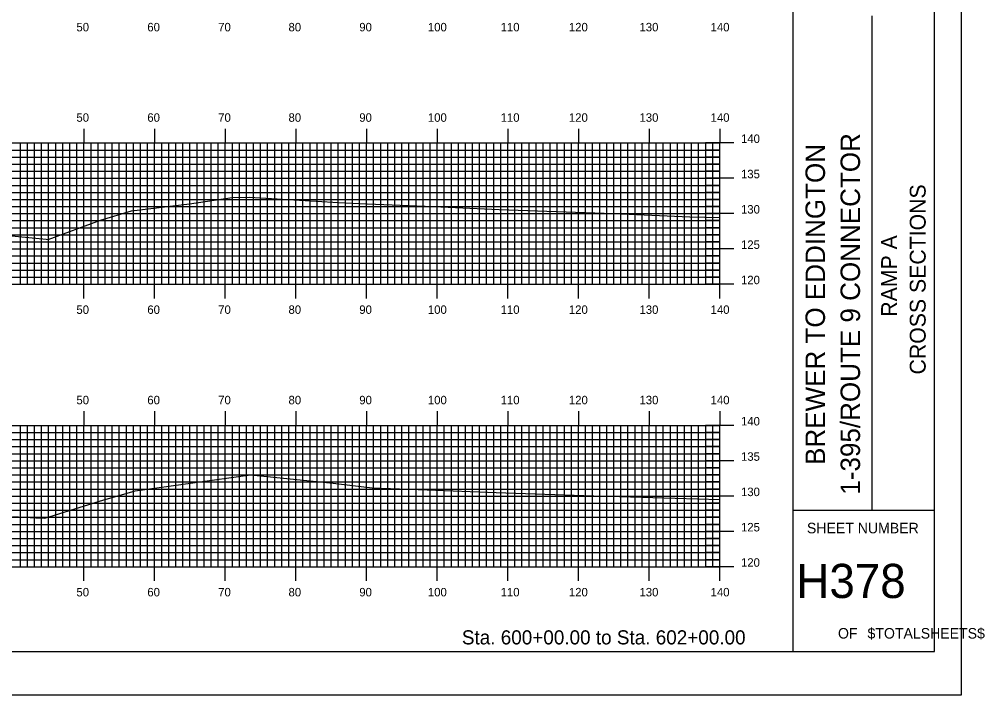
# Model space of a CAD drawing. Extents: x 841388 to 841731, y 363538 to 363758.
# Drawn here: x 841594.7 to 841731.4, y 363537.6 to 363633.2 of the extents above; entities that cross this region are included whole.
import ezdxf

# ---------------------------------------------------------------- set-up
doc = ezdxf.new("R2010")
doc.units = 0
for name, color, linetype in [('BORDER', 7, 'Continuous'), ('H_V ANNOTATION', 7, 'Continuous'), ('MAJOR', 7, 'Continuous'), ('MINOR', 7, 'Continuous'), ('PLOT BOUNDARY', 7, 'Continuous'), ('S_Roadway_Centerline', 7, 'Continuous')]:
    doc.layers.add(name, color=color, linetype=linetype)

msp = doc.modelspace()

# ---------------------------------------------------------------- linework, layer by layer
at = {"layer": 'BORDER'}
for p, q in [((841704.26, 363543.72), (841704.26, 363753.72)), ((841715.44, 363563.73), (841715.44, 363633.73)), ((841704.26, 363563.73), (841724.26, 363563.73))]:
    msp.add_line(p, q, dxfattribs=at)
msp.add_lwpolyline([(841404.26, 363543.72), (841724.26, 363543.72), (841724.26, 363753.72), (841404.26, 363753.72)], close=True, dxfattribs=at)
at = {"layer": 'MAJOR'}
for p, q in [((841603.86, 363617.73), (841603.86, 363615.72)), ((841613.86, 363617.73), (841613.86, 363615.72)), ((841623.86, 363617.73), (841623.86, 363615.72)), ((841633.86, 363617.73), (841633.86, 363615.72)), ((841643.86, 363617.73), (841643.86, 363615.72)), ((841653.86, 363617.73), (841653.86, 363615.72)), ((841663.86, 363617.73), (841663.86, 363615.72)), ((841673.86, 363617.73), (841673.86, 363615.72)), ((841683.86, 363617.73), (841683.86, 363615.72)), ((841693.86, 363617.73), (841693.86, 363615.72)), ((841413.86, 363615.72), (841693.86, 363615.72)), ((841413.86, 363615.72), (841693.86, 363615.72)), ((841603.86, 363595.72), (841603.86, 363615.72)), ((841613.86, 363595.72), (841613.86, 363615.72)), ((841623.86, 363595.72), (841623.86, 363615.72)), ((841633.86, 363595.72), (841633.86, 363615.72)), ((841643.86, 363595.72), (841643.86, 363615.72)), ((841653.86, 363595.72), (841653.86, 363615.72)), ((841663.86, 363595.72), (841663.86, 363615.72)), ((841673.86, 363595.72), (841673.86, 363615.72)), ((841683.86, 363595.72), (841683.86, 363615.72)), ((841695.86, 363615.72), (841691.85, 363615.72)), ((841693.86, 363595.72), (841693.86, 363615.72)), ((841693.86, 363595.72), (841693.86, 363615.72)), ((841413.86, 363610.72), (841693.86, 363610.72)), ((841695.86, 363610.72), (841691.85, 363610.72)), ((841413.86, 363605.72), (841693.86, 363605.72)), ((841695.86, 363605.72), (841691.85, 363605.72)), ((841413.86, 363600.72), (841693.86, 363600.72)), ((841695.86, 363600.72), (841691.85, 363600.72)), ((841413.86, 363595.72), (841693.86, 363595.72)), ((841413.86, 363595.72), (841693.86, 363595.72)), ((841603.86, 363593.72), (841603.86, 363595.72)), ((841613.86, 363593.72), (841613.86, 363595.72)), ((841623.86, 363593.72), (841623.86, 363595.72)), ((841633.86, 363593.72), (841633.86, 363595.72)), ((841643.86, 363593.72), (841643.86, 363595.72)), ((841653.86, 363593.72), (841653.86, 363595.72)), ((841663.86, 363593.72), (841663.86, 363595.72)), ((841673.86, 363593.72), (841673.86, 363595.72)), ((841683.86, 363593.72), (841683.86, 363595.72)), ((841695.86, 363595.72), (841691.85, 363595.72)), ((841693.86, 363593.72), (841693.86, 363595.72)), ((841603.86, 363577.73), (841603.86, 363575.72)), ((841613.86, 363577.73), (841613.86, 363575.72)), ((841623.86, 363577.73), (841623.86, 363575.72)), ((841633.86, 363577.73), (841633.86, 363575.72)), ((841643.86, 363577.73), (841643.86, 363575.72)), ((841653.86, 363577.73), (841653.86, 363575.72)), ((841663.86, 363577.73), (841663.86, 363575.72)), ((841673.86, 363577.73), (841673.86, 363575.72)), ((841683.86, 363577.73), (841683.86, 363575.72)), ((841693.86, 363577.73), (841693.86, 363575.72)), ((841413.86, 363575.72), (841693.86, 363575.72)), ((841413.86, 363575.72), (841693.86, 363575.72)), ((841603.86, 363555.72), (841603.86, 363575.72)), ((841613.86, 363555.72), (841613.86, 363575.72)), ((841623.86, 363555.72), (841623.86, 363575.72)), ((841633.86, 363555.72), (841633.86, 363575.72)), ((841643.86, 363555.72), (841643.86, 363575.72)), ((841653.86, 363555.72), (841653.86, 363575.72)), ((841663.86, 363555.72), (841663.86, 363575.72)), ((841673.86, 363555.72), (841673.86, 363575.72)), ((841683.86, 363555.72), (841683.86, 363575.72)), ((841695.86, 363575.72), (841691.85, 363575.72)), ((841693.86, 363555.72), (841693.86, 363575.72)), ((841693.86, 363555.72), (841693.86, 363575.72)), ((841413.86, 363570.72), (841693.86, 363570.72)), ((841695.86, 363570.72), (841691.85, 363570.72)), ((841413.86, 363565.72), (841693.86, 363565.72)), ((841695.86, 363565.72), (841691.85, 363565.72)), ((841413.86, 363560.72), (841693.86, 363560.72)), ((841695.86, 363560.72), (841691.85, 363560.72)), ((841413.86, 363555.72), (841693.86, 363555.72)), ((841413.86, 363555.72), (841693.86, 363555.72)), ((841603.86, 363553.72), (841603.86, 363555.72)), ((841613.86, 363553.72), (841613.86, 363555.72)), ((841623.86, 363553.72), (841623.86, 363555.72)), ((841633.86, 363553.72), (841633.86, 363555.72)), ((841643.86, 363553.72), (841643.86, 363555.72)), ((841653.86, 363553.72), (841653.86, 363555.72)), ((841663.86, 363553.72), (841663.86, 363555.72)), ((841673.86, 363553.72), (841673.86, 363555.72)), ((841683.86, 363553.72), (841683.86, 363555.72)), ((841695.86, 363555.72), (841691.85, 363555.72)), ((841693.86, 363553.72), (841693.86, 363555.72))]:
    msp.add_line(p, q, dxfattribs=at)
at = {"layer": 'MINOR'}
for p, q in [((841594.86, 363595.72), (841594.86, 363615.72)), ((841595.86, 363595.72), (841595.86, 363615.72)), ((841596.86, 363595.72), (841596.86, 363615.72)), ((841597.86, 363595.72), (841597.86, 363615.72)), ((841598.86, 363595.72), (841598.86, 363615.72)), ((841599.86, 363595.72), (841599.86, 363615.72)), ((841600.86, 363595.72), (841600.86, 363615.72)), ((841601.86, 363595.72), (841601.86, 363615.72)), ((841602.86, 363595.72), (841602.86, 363615.72)), ((841604.86, 363595.72), (841604.86, 363615.72)), ((841605.86, 363595.72), (841605.86, 363615.72)), ((841606.86, 363595.72), (841606.86, 363615.72)), ((841607.86, 363595.72), (841607.86, 363615.72)), ((841608.86, 363595.72), (841608.86, 363615.72)), ((841609.86, 363595.72), (841609.86, 363615.72)), ((841610.86, 363595.72), (841610.86, 363615.72)), ((841611.86, 363595.72), (841611.86, 363615.72)), ((841612.86, 363595.72), (841612.86, 363615.72)), ((841614.86, 363595.72), (841614.86, 363615.72)), ((841615.86, 363595.72), (841615.86, 363615.72)), ((841616.86, 363595.72), (841616.86, 363615.72)), ((841617.86, 363595.72), (841617.86, 363615.72)), ((841618.86, 363595.72), (841618.86, 363615.72)), ((841619.86, 363595.72), (841619.86, 363615.72)), ((841620.86, 363595.72), (841620.86, 363615.72)), ((841621.86, 363595.72), (841621.86, 363615.72)), ((841622.86, 363595.72), (841622.86, 363615.72)), ((841624.86, 363595.72), (841624.86, 363615.72)), ((841625.86, 363595.72), (841625.86, 363615.72)), ((841626.86, 363595.72), (841626.86, 363615.72)), ((841627.86, 363595.72), (841627.86, 363615.72)), ((841628.86, 363595.72), (841628.86, 363615.72)), ((841629.86, 363595.72), (841629.86, 363615.72)), ((841630.86, 363595.72), (841630.86, 363615.72)), ((841631.86, 363595.72), (841631.86, 363615.72)), ((841632.86, 363595.72), (841632.86, 363615.72)), ((841634.86, 363595.72), (841634.86, 363615.72)), ((841635.86, 363595.72), (841635.86, 363615.72)), ((841636.86, 363595.72), (841636.86, 363615.72)), ((841637.86, 363595.72), (841637.86, 363615.72)), ((841638.86, 363595.72), (841638.86, 363615.72)), ((841639.86, 363595.72), (841639.86, 363615.72)), ((841640.86, 363595.72), (841640.86, 363615.72)), ((841641.86, 363595.72), (841641.86, 363615.72)), ((841642.86, 363595.72), (841642.86, 363615.72)), ((841644.86, 363595.72), (841644.86, 363615.72)), ((841645.86, 363595.72), (841645.86, 363615.72)), ((841646.86, 363595.72), (841646.86, 363615.72)), ((841647.86, 363595.72), (841647.86, 363615.72)), ((841648.86, 363595.72), (841648.86, 363615.72)), ((841649.86, 363595.72), (841649.86, 363615.72)), ((841650.86, 363595.72), (841650.86, 363615.72)), ((841651.86, 363595.72), (841651.86, 363615.72)), ((841652.86, 363595.72), (841652.86, 363615.72)), ((841654.86, 363595.72), (841654.86, 363615.72)), ((841655.86, 363595.72), (841655.86, 363615.72)), ((841656.86, 363595.72), (841656.86, 363615.72)), ((841657.86, 363595.72), (841657.86, 363615.72)), ((841658.86, 363595.72), (841658.86, 363615.72)), ((841659.86, 363595.72), (841659.86, 363615.72)), ((841660.86, 363595.72), (841660.86, 363615.72)), ((841661.86, 363595.72), (841661.86, 363615.72)), ((841662.86, 363595.72), (841662.86, 363615.72)), ((841664.86, 363595.72), (841664.86, 363615.72)), ((841665.86, 363595.72), (841665.86, 363615.72)), ((841666.86, 363595.72), (841666.86, 363615.72)), ((841667.86, 363595.72), (841667.86, 363615.72)), ((841668.86, 363595.72), (841668.86, 363615.72)), ((841669.86, 363595.72), (841669.86, 363615.72)), ((841670.86, 363595.72), (841670.86, 363615.72)), ((841671.86, 363595.72), (841671.86, 363615.72)), ((841672.86, 363595.72), (841672.86, 363615.72)), ((841674.86, 363595.72), (841674.86, 363615.72)), ((841675.86, 363595.72), (841675.86, 363615.72)), ((841676.86, 363595.72), (841676.86, 363615.72)), ((841677.86, 363595.72), (841677.86, 363615.72)), ((841678.86, 363595.72), (841678.86, 363615.72)), ((841679.86, 363595.72), (841679.86, 363615.72)), ((841680.86, 363595.72), (841680.86, 363615.72)), ((841681.86, 363595.72), (841681.86, 363615.72)), ((841682.86, 363595.72), (841682.86, 363615.72)), ((841684.86, 363595.72), (841684.86, 363615.72)), ((841685.86, 363595.72), (841685.86, 363615.72)), ((841686.86, 363595.72), (841686.86, 363615.72)), ((841687.86, 363595.72), (841687.86, 363615.72)), ((841688.86, 363595.72), (841688.86, 363615.72)), ((841689.86, 363595.72), (841689.86, 363615.72)), ((841690.86, 363595.72), (841690.86, 363615.72)), ((841691.86, 363595.72), (841691.86, 363615.72)), ((841692.86, 363595.72), (841692.86, 363615.72)), ((841413.86, 363614.72), (841693.86, 363614.72)), ((841693.86, 363614.72), (841691.85, 363614.72)), ((841413.86, 363613.72), (841693.86, 363613.72)), ((841693.86, 363613.72), (841691.85, 363613.72)), ((841413.86, 363612.72), (841693.86, 363612.72)), ((841413.86, 363611.72), (841693.86, 363611.72)), ((841693.86, 363612.72), (841691.85, 363612.72)), ((841693.86, 363611.72), (841691.85, 363611.72)), ((841413.86, 363609.72), (841693.86, 363609.72)), ((841693.86, 363609.72), (841691.85, 363609.72)), ((841413.86, 363608.72), (841693.86, 363608.72)), ((841413.86, 363607.72), (841693.86, 363607.72)), ((841693.86, 363608.72), (841691.85, 363608.72)), ((841693.86, 363607.72), (841691.85, 363607.72)), ((841413.86, 363606.72), (841693.86, 363606.72)), ((841693.86, 363606.72), (841691.85, 363606.72)), ((841413.86, 363604.72), (841693.86, 363604.72)), ((841413.86, 363603.72), (841693.86, 363603.72)), ((841693.86, 363604.72), (841691.85, 363604.72)), ((841693.86, 363603.72), (841691.85, 363603.72)), ((841413.86, 363602.72), (841693.86, 363602.72)), ((841693.86, 363602.72), (841691.85, 363602.72)), ((841413.86, 363601.72), (841693.86, 363601.72)), ((841693.86, 363601.72), (841691.85, 363601.72)), ((841413.86, 363599.72), (841693.86, 363599.72)), ((841693.86, 363599.72), (841691.85, 363599.72)), ((841413.86, 363598.72), (841693.86, 363598.72)), ((841693.86, 363598.72), (841691.85, 363598.72)), ((841413.86, 363597.72), (841693.86, 363597.72)), ((841413.86, 363596.72), (841693.86, 363596.72)), ((841693.86, 363597.72), (841691.85, 363597.72)), ((841693.86, 363596.72), (841691.85, 363596.72)), ((841413.86, 363574.72), (841693.86, 363574.72)), ((841594.86, 363555.72), (841594.86, 363575.72)), ((841595.86, 363555.72), (841595.86, 363575.72)), ((841596.86, 363555.72), (841596.86, 363575.72)), ((841597.86, 363555.72), (841597.86, 363575.72)), ((841598.86, 363555.72), (841598.86, 363575.72)), ((841599.86, 363555.72), (841599.86, 363575.72)), ((841600.86, 363555.72), (841600.86, 363575.72)), ((841601.86, 363555.72), (841601.86, 363575.72)), ((841602.86, 363555.72), (841602.86, 363575.72)), ((841604.86, 363555.72), (841604.86, 363575.72)), ((841605.86, 363555.72), (841605.86, 363575.72)), ((841606.86, 363555.72), (841606.86, 363575.72)), ((841607.86, 363555.72), (841607.86, 363575.72)), ((841608.86, 363555.72), (841608.86, 363575.72)), ((841609.86, 363555.72), (841609.86, 363575.72)), ((841610.86, 363555.72), (841610.86, 363575.72)), ((841611.86, 363555.72), (841611.86, 363575.72)), ((841612.86, 363555.72), (841612.86, 363575.72)), ((841614.86, 363555.72), (841614.86, 363575.72)), ((841615.86, 363555.72), (841615.86, 363575.72)), ((841616.86, 363555.72), (841616.86, 363575.72)), ((841617.86, 363555.72), (841617.86, 363575.72)), ((841618.86, 363555.72), (841618.86, 363575.72)), ((841619.86, 363555.72), (841619.86, 363575.72)), ((841620.86, 363555.72), (841620.86, 363575.72)), ((841621.86, 363555.72), (841621.86, 363575.72)), ((841622.86, 363555.72), (841622.86, 363575.72)), ((841624.86, 363555.72), (841624.86, 363575.72)), ((841625.86, 363555.72), (841625.86, 363575.72)), ((841626.86, 363555.72), (841626.86, 363575.72)), ((841627.86, 363555.72), (841627.86, 363575.72)), ((841628.86, 363555.72), (841628.86, 363575.72)), ((841629.86, 363555.72), (841629.86, 363575.72)), ((841630.86, 363555.72), (841630.86, 363575.72)), ((841631.86, 363555.72), (841631.86, 363575.72)), ((841632.86, 363555.72), (841632.86, 363575.72)), ((841634.86, 363555.72), (841634.86, 363575.72)), ((841635.86, 363555.72), (841635.86, 363575.72)), ((841636.86, 363555.72), (841636.86, 363575.72)), ((841637.86, 363555.72), (841637.86, 363575.72)), ((841638.86, 363555.72), (841638.86, 363575.72)), ((841639.86, 363555.72), (841639.86, 363575.72)), ((841640.86, 363555.72), (841640.86, 363575.72)), ((841641.86, 363555.72), (841641.86, 363575.72)), ((841642.86, 363555.72), (841642.86, 363575.72)), ((841644.86, 363555.72), (841644.86, 363575.72)), ((841645.86, 363555.72), (841645.86, 363575.72)), ((841646.86, 363555.72), (841646.86, 363575.72)), ((841647.86, 363555.72), (841647.86, 363575.72)), ((841648.86, 363555.72), (841648.86, 363575.72)), ((841649.86, 363555.72), (841649.86, 363575.72)), ((841650.86, 363555.72), (841650.86, 363575.72)), ((841651.86, 363555.72), (841651.86, 363575.72)), ((841652.86, 363555.72), (841652.86, 363575.72)), ((841654.86, 363555.72), (841654.86, 363575.72)), ((841655.86, 363555.72), (841655.86, 363575.72)), ((841656.86, 363555.72), (841656.86, 363575.72)), ((841657.86, 363555.72), (841657.86, 363575.72)), ((841658.86, 363555.72), (841658.86, 363575.72)), ((841659.86, 363555.72), (841659.86, 363575.72)), ((841660.86, 363555.72), (841660.86, 363575.72)), ((841661.86, 363555.72), (841661.86, 363575.72)), ((841662.86, 363555.72), (841662.86, 363575.72)), ((841664.86, 363555.72), (841664.86, 363575.72)), ((841665.86, 363555.72), (841665.86, 363575.72)), ((841666.86, 363555.72), (841666.86, 363575.72)), ((841667.86, 363555.72), (841667.86, 363575.72)), ((841668.86, 363555.72), (841668.86, 363575.72)), ((841669.86, 363555.72), (841669.86, 363575.72)), ((841670.86, 363555.72), (841670.86, 363575.72)), ((841671.86, 363555.72), (841671.86, 363575.72)), ((841672.86, 363555.72), (841672.86, 363575.72)), ((841674.86, 363555.72), (841674.86, 363575.72)), ((841675.86, 363555.72), (841675.86, 363575.72)), ((841676.86, 363555.72), (841676.86, 363575.72)), ((841677.86, 363555.72), (841677.86, 363575.72)), ((841678.86, 363555.72), (841678.86, 363575.72)), ((841679.86, 363555.72), (841679.86, 363575.72)), ((841680.86, 363555.72), (841680.86, 363575.72)), ((841681.86, 363555.72), (841681.86, 363575.72)), ((841682.86, 363555.72), (841682.86, 363575.72)), ((841684.86, 363555.72), (841684.86, 363575.72)), ((841685.86, 363555.72), (841685.86, 363575.72)), ((841686.86, 363555.72), (841686.86, 363575.72)), ((841687.86, 363555.72), (841687.86, 363575.72)), ((841688.86, 363555.72), (841688.86, 363575.72)), ((841689.86, 363555.72), (841689.86, 363575.72)), ((841690.86, 363555.72), (841690.86, 363575.72)), ((841693.86, 363574.72), (841691.85, 363574.72)), ((841691.86, 363555.72), (841691.86, 363575.72)), ((841692.86, 363555.72), (841692.86, 363575.72)), ((841413.86, 363573.72), (841693.86, 363573.72)), ((841693.86, 363573.72), (841691.85, 363573.72)), ((841413.86, 363572.72), (841693.86, 363572.72)), ((841693.86, 363572.72), (841691.85, 363572.72)), ((841413.86, 363571.72), (841693.86, 363571.72)), ((841693.86, 363571.72), (841691.85, 363571.72)), ((841413.86, 363569.72), (841693.86, 363569.72)), ((841693.86, 363569.72), (841691.85, 363569.72)), ((841413.86, 363568.72), (841693.86, 363568.72)), ((841693.86, 363568.72), (841691.85, 363568.72)), ((841413.86, 363567.72), (841693.86, 363567.72)), ((841413.86, 363566.72), (841693.86, 363566.72)), ((841693.86, 363567.72), (841691.85, 363567.72)), ((841693.86, 363566.72), (841691.85, 363566.72)), ((841413.86, 363564.72), (841693.86, 363564.72)), ((841693.86, 363564.72), (841691.85, 363564.72)), ((841413.86, 363563.72), (841693.86, 363563.72)), ((841413.86, 363562.72), (841693.86, 363562.72)), ((841693.86, 363563.72), (841691.85, 363563.72)), ((841693.86, 363562.72), (841691.85, 363562.72)), ((841413.86, 363561.72), (841693.86, 363561.72)), ((841693.86, 363561.72), (841691.85, 363561.72)), ((841413.86, 363559.72), (841693.86, 363559.72)), ((841693.86, 363559.72), (841691.85, 363559.72)), ((841413.86, 363558.72), (841693.86, 363558.72)), ((841693.86, 363558.72), (841691.85, 363558.72)), ((841413.86, 363557.72), (841693.86, 363557.72)), ((841693.86, 363557.72), (841691.85, 363557.72)), ((841413.86, 363556.72), (841693.86, 363556.72)), ((841693.86, 363556.72), (841691.85, 363556.72))]:
    msp.add_line(p, q, dxfattribs=at)
at = {"layer": 'PLOT BOUNDARY'}
msp.add_lwpolyline([(841388.07, 363537.6), (841728.07, 363537.6), (841728.07, 363757.6), (841388.07, 363757.6)], close=True, dxfattribs=at)
at = {"layer": 'S_Roadway_Centerline'}
for points in [[(841592.16, 363602.72), (841598.49, 363602.11), (841598.8, 363602.07), (841606.19, 363604.79), (841610.61, 363606.12), (841618.8, 363607.08), (841624.82, 363608), (841627.25, 363608.03), (841639.87, 363607.27), (841642.75, 363607.13), (841653.34, 363606.71), (841662.61, 363606.31), (841678.88, 363605.72), (841689.62, 363605.24), (841693.86, 363605.18)], [(841593.81, 363562.85), (841597.04, 363562.63), (841598.32, 363562.61), (841606.66, 363565.18), (841608.84, 363565.79), (841611.09, 363566.45), (841627.42, 363568.73), (841639.15, 363567.56), (841644.67, 363566.88), (841652.43, 363566.61), (841662.22, 363566.22), (841677.38, 363565.72), (841677.56, 363565.71), (841677.67, 363565.7), (841678.08, 363565.69), (841693.86, 363565.22)]]:
    msp.add_lwpolyline(points, dxfattribs=at)

# ---------------------------------------------------------------- texts
at = {"layer": 'BORDER'}
for s, height, p in [('1-395/ROUTE 9 CONNECTOR', 2.7557, (841713.71, 363565.92)), ('BREWER TO EDDINGTON', 2.7557, (841708.75, 363570.13)), ('CROSS SECTIONS', 2.25, (841723, 363582.94)), ('RAMP A', 2.25, (841718.95, 363591.12))]:
    msp.add_text(s, height=height, rotation=90, dxfattribs=at).set_placement(p)
for s, height, p in [('SHEET NUMBER', 1.4905, (841706.19, 363560.45)), ('H378', 4.839, (841704.7, 363551.29)), ('OF', 1.491, (841710.59, 363545.55)), ('$TOTALSHEETS$', 1.4905, (841714.77, 363545.55))]:
    msp.add_text(s, height=height, dxfattribs=at).set_placement(p)
at = {"layer": 'H_V ANNOTATION'}
for s, height, p in [('50', 1.2, (841602.79, 363631.52)), ('60', 1.2, (841612.83, 363631.52)), ('70', 1.2, (841622.86, 363631.52)), ('80', 1.2, (841632.81, 363631.52)), ('90', 1.2, (841642.83, 363631.52)), ('100', 1.2, (841652.54, 363631.52)), ('110', 1.2, (841662.84, 363631.52)), ('120', 1.2, (841672.5, 363631.52)), ('130', 1.2, (841682.49, 363631.52)), ('140', 1.2, (841692.56, 363631.52)), ('50', 1.2, (841602.79, 363618.72)), ('60', 1.2, (841612.83, 363618.72)), ('70', 1.2, (841622.86, 363618.72)), ('80', 1.2, (841632.81, 363618.72)), ('90', 1.2, (841642.83, 363618.72)), ('100', 1.2, (841652.54, 363618.72)), ('110', 1.2, (841662.84, 363618.72)), ('120', 1.2, (841672.5, 363618.72)), ('130', 1.2, (841682.49, 363618.72)), ('140', 1.2, (841692.56, 363618.72)), ('140', 1.2, (841696.86, 363615.72)), ('135', 1.2, (841696.86, 363610.72)), ('130', 1.2, (841696.86, 363605.72)), ('125', 1.2, (841696.86, 363600.72)), ('120', 1.2, (841696.86, 363595.72)), ('50', 1.2, (841602.79, 363591.52)), ('60', 1.2, (841612.83, 363591.52)), ('70', 1.2, (841622.86, 363591.52)), ('80', 1.2, (841632.81, 363591.52)), ('90', 1.2, (841642.83, 363591.52)), ('100', 1.2, (841652.54, 363591.52)), ('110', 1.2, (841662.84, 363591.52)), ('120', 1.2, (841672.5, 363591.52)), ('130', 1.2, (841682.49, 363591.52)), ('140', 1.2, (841692.56, 363591.52)), ('50', 1.2, (841602.79, 363578.72)), ('60', 1.2, (841612.83, 363578.72)), ('70', 1.2, (841622.86, 363578.72)), ('80', 1.2, (841632.81, 363578.72)), ('90', 1.2, (841642.83, 363578.72)), ('100', 1.2, (841652.54, 363578.72)), ('110', 1.2, (841662.84, 363578.72)), ('120', 1.2, (841672.5, 363578.72)), ('130', 1.2, (841682.49, 363578.72)), ('140', 1.2, (841692.56, 363578.72)), ('140', 1.2, (841696.86, 363575.72)), ('135', 1.2, (841696.86, 363570.72)), ('130', 1.2, (841696.86, 363565.72)), ('125', 1.2, (841696.86, 363560.72)), ('120', 1.2, (841696.86, 363555.72)), ('50', 1.2, (841602.79, 363551.52)), ('60', 1.2, (841612.83, 363551.52)), ('70', 1.2, (841622.86, 363551.52)), ('80', 1.2, (841632.81, 363551.52)), ('90', 1.2, (841642.83, 363551.52)), ('100', 1.2, (841652.54, 363551.52)), ('110', 1.2, (841662.84, 363551.52)), ('120', 1.2, (841672.5, 363551.52)), ('130', 1.2, (841682.49, 363551.52)), ('140', 1.2, (841692.56, 363551.52)), ('Sta. 600+00.00 to Sta. 602+00.00', 2.0004, (841657.35, 363544.72))]:
    msp.add_text(s, height=height, dxfattribs=at).set_placement(p)

doc.saveas('drawing.dxf')
